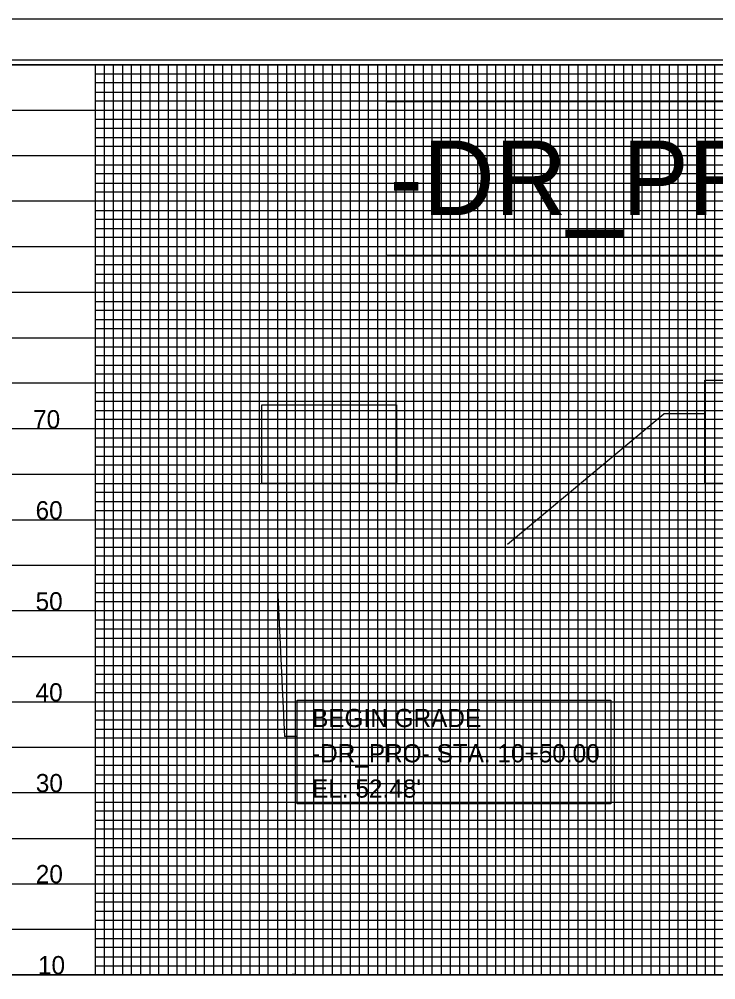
# Model space of a CAD drawing. Extents: x 1019474 to 1021158, y 503201 to 504732.
# Drawn here: x 1020350 to 1020732, y 503773 to 504301 of the extents above; entities that cross this region are included whole.
import ezdxf

# ---------------------------------------------------------------- set-up
doc = ezdxf.new("R2010")
doc.units = 0
for name, color, linetype in [('Exist Vertical Profile Vertical Axis Label', 7, 'Continuous'), ('Prop Grid Mask', 7, 'Continuous'), ('Prop Vertical Profile Grade Label', 7, 'Continuous'), ('Prop VPI Label', 7, 'Continuous'), ('Scratch_Level_0', 7, 'Continuous'), ('Sheet Cutting Line CELL', 7, 'Continuous'), ('Sheet Layout Profile Border Port 1', 7, 'Continuous'), ('Sheet Layout Profile Border Port 2', 7, 'Continuous'), ('Sheet Plot Border Inside CELL', 7, 'Continuous'), ('Sheet Plot Border Outside CELL', 7, 'Continuous'), ('Sheet Profile CELL', 7, 'Continuous'), ('Sheet Profile Grid Major CELL', 7, 'Continuous'), ('Sheet Profile Grid Middle CELL', 7, 'Continuous'), ('Sheet Profile Grid Minor CELL', 7, 'Continuous')]:
    doc.layers.add(name, color=color, linetype=linetype)

msp = doc.modelspace()

# ---------------------------------------------------------------- linework, layer by layer
at = {"layer": 'Prop Grid Mask'}
for points in [[(1020551.1, 504255.58), (1020851.32, 504255.58), (1020851.32, 504170.85), (1020551.1, 504170.85)], [(1020725.91, 504102.51), (1020898.5, 504102.51), (1020898.5, 504045.7), (1020725.91, 504045.7)], [(1020482.77, 504088.87), (1020556.58, 504088.87), (1020556.58, 504045.64), (1020482.77, 504045.64)], [(1020502.03, 503926.64), (1020674.35, 503926.64), (1020674.35, 503869.72), (1020502.03, 503869.72)]]:
    msp.add_lwpolyline(points, close=True, dxfattribs=at)
at = {"layer": 'Prop Vertical Profile Grade Label'}
for p, q in [((1020617.51, 504012.38), (1020703.32, 504083.87)), ((1020726.37, 504083.87), (1020703.32, 504083.87)), ((1020491.22, 503988.11), (1020495.21, 503906.65)), ((1020502.12, 503906.65), (1020495.21, 503906.65))]:
    msp.add_line(p, q, dxfattribs=at)
at = {"layer": 'Scratch_Level_0'}
msp.add_lwpolyline([(1019691.22, 503775.7), (1019691.22, 504275.7), (1020941.22, 504275.7), (1020941.17, 504114.65), (1021091.22, 504114.65), (1021091.22, 503775.7)], close=True, dxfattribs=at)
at = {"layer": 'Sheet Cutting Line CELL'}
msp.add_line((1021158.22, 504300.7), (1019474.22, 504300.7), dxfattribs=at)
at = {"layer": 'Sheet Layout Profile Border Port 1'}
msp.add_lwpolyline([(1019691.22, 504114.65), (1019691.22, 503775.7), (1021091.22, 503775.7), (1021091.22, 504114.65)], dxfattribs=at)
at = {"layer": 'Sheet Layout Profile Border Port 2'}
msp.add_lwpolyline([(1019691.22, 504275.7), (1020941.22, 504275.7), (1020941.17, 504114.65), (1021091.22, 504114.65), (1021091.22, 503775.7), (1019691.22, 503775.7)], close=True, dxfattribs=at)
at = {"layer": 'Sheet Plot Border Inside CELL'}
msp.add_lwpolyline([(1019487.22, 503223.15), (1021153.72, 503223.15), (1021153.72, 504278.25), (1019487.22, 504278.25)], close=True, dxfattribs=at)
at = {"layer": 'Sheet Plot Border Outside CELL'}
msp.add_lwpolyline([(1019474.22, 503200.7), (1021158.22, 503200.7), (1021158.22, 504300.7), (1019474.22, 504300.7)], close=True, dxfattribs=at)
at = {"layer": 'Sheet Profile CELL'}
msp.add_line((1019641.22, 503775.7), (1021141.22, 503775.7), dxfattribs=at)
msp.add_lwpolyline([(1021141.22, 504275.7), (1019641.22, 504275.7), (1019641.22, 503225.7), (1021141.22, 503225.7)], close=True, dxfattribs=at)
at = {"layer": 'Sheet Profile Grid Major CELL'}
for p, q in [((1020341.22, 504275.7), (1020391.22, 504275.7)), ((1020391.22, 504275.7), (1020391.22, 503775.7)), ((1020441.22, 503775.7), (1020441.22, 504275.7)), ((1020441.22, 504275.7), (1020491.22, 504275.7)), ((1020491.22, 504275.7), (1020491.22, 503775.7)), ((1020541.22, 503775.7), (1020541.22, 504275.7)), ((1020541.22, 504275.7), (1020591.22, 504275.7)), ((1020591.22, 504275.7), (1020591.22, 503775.7)), ((1020641.22, 503775.7), (1020641.22, 504275.7)), ((1020641.22, 504275.7), (1020691.22, 504275.7)), ((1020691.22, 504275.7), (1020691.22, 503775.7)), ((1020391.22, 503775.7), (1020441.22, 503775.7)), ((1020491.22, 503775.7), (1020541.22, 503775.7)), ((1020591.22, 503775.7), (1020641.22, 503775.7)), ((1020691.22, 503775.7), (1020741.22, 503775.7))]:
    msp.add_line(p, q, dxfattribs=at)
for points in [[(1020941.17, 504225.7), (1019641.22, 504225.7)], [(1020941.17, 504175.7), (1019641.22, 504175.7), (1019641.22, 504125.7), (1020941.17, 504125.7)], [(1021141.22, 504075.7), (1019641.22, 504075.7), (1019641.22, 504025.7), (1021141.22, 504025.7)], [(1021141.22, 503975.7), (1019641.22, 503975.7), (1019641.22, 503925.7), (1021141.22, 503925.7)], [(1021141.22, 503875.7), (1019641.22, 503875.7), (1019641.22, 503875.7), (1019641.22, 503825.7), (1021141.22, 503825.7)]]:
    msp.add_lwpolyline(points, dxfattribs=at)
at = {"layer": 'Sheet Profile Grid Middle CELL'}
for p, q in [((1020466.22, 503775.7), (1020466.22, 504275.7)), ((1020466.22, 504275.7), (1020516.22, 504275.7)), ((1020516.22, 504275.7), (1020516.22, 503775.7)), ((1020566.22, 503775.7), (1020566.22, 504275.7)), ((1020566.22, 504275.7), (1020616.22, 504275.7)), ((1020616.22, 504275.7), (1020616.22, 503775.7)), ((1020666.22, 503775.7), (1020666.22, 504275.7)), ((1020666.22, 504275.7), (1020716.22, 504275.7)), ((1020716.22, 504275.7), (1020716.22, 503775.7)), ((1020441.22, 503775.7), (1020466.22, 503775.7)), ((1020516.22, 503775.7), (1020566.22, 503775.7)), ((1020616.22, 503775.7), (1020666.22, 503775.7)), ((1020716.22, 503775.7), (1020766.22, 503775.7))]:
    msp.add_line(p, q, dxfattribs=at)
for points in [[(1020391.22, 503775.7), (1020416.22, 503775.7), (1020416.22, 504275.7), (1020441.22, 504275.7)], [(1019641.22, 504250.7), (1020941.22, 504250.7)], [(1020941.17, 504200.7), (1019641.22, 504200.7), (1019641.22, 504150.7), (1020941.17, 504150.7)], [(1021141.22, 504100.7), (1019641.22, 504100.7), (1019641.22, 504050.7), (1021141.22, 504050.7)], [(1021141.22, 504000.7), (1019641.22, 504000.7), (1019641.22, 503950.7), (1021141.22, 503950.7)], [(1021141.22, 503900.7), (1019641.22, 503900.7), (1019641.22, 503850.7), (1021141.22, 503850.7)], [(1021141.22, 503800.7), (1019641.22, 503800.7)]]:
    msp.add_lwpolyline(points, dxfattribs=at)
at = {"layer": 'Sheet Profile Grid Minor CELL'}
for p, q in [((1020391.22, 504270.7), (1020441.22, 504270.7)), ((1020441.22, 504270.7), (1020941.22, 504270.7)), ((1020441.22, 504265.7), (1020391.22, 504265.7)), ((1020941.22, 504265.7), (1020441.22, 504265.7)), ((1020391.22, 504260.7), (1020441.22, 504260.7)), ((1020441.22, 504260.7), (1020941.22, 504260.7)), ((1020441.22, 504255.7), (1020391.22, 504255.7)), ((1020941.22, 504255.7), (1020441.22, 504255.7)), ((1020391.22, 504245.7), (1020441.22, 504245.7)), ((1020441.22, 504245.7), (1020941.22, 504245.7)), ((1020441.22, 504240.7), (1020391.22, 504240.7)), ((1020941.22, 504240.7), (1020441.22, 504240.7)), ((1020391.22, 504235.7), (1020441.22, 504235.7)), ((1020441.22, 504235.7), (1020941.22, 504235.7)), ((1020441.22, 504230.7), (1020391.22, 504230.7)), ((1020941.22, 504230.7), (1020441.22, 504230.7)), ((1020391.22, 504220.7), (1020441.22, 504220.7)), ((1020441.22, 504220.7), (1020941.17, 504220.7)), ((1020441.22, 504215.7), (1020391.22, 504215.7)), ((1020941.17, 504215.7), (1020441.22, 504215.7)), ((1020391.22, 504210.7), (1020441.22, 504210.7)), ((1020441.22, 504210.7), (1020941.17, 504210.7)), ((1020441.22, 504205.7), (1020391.22, 504205.7)), ((1020941.17, 504205.7), (1020441.22, 504205.7)), ((1020391.22, 504195.7), (1020441.22, 504195.7)), ((1020441.22, 504195.7), (1020941.17, 504195.7)), ((1020441.22, 504190.7), (1020391.22, 504190.7)), ((1020941.17, 504190.7), (1020441.22, 504190.7)), ((1020391.22, 504185.7), (1020441.22, 504185.7)), ((1020441.22, 504185.7), (1020941.17, 504185.7)), ((1020441.22, 504180.7), (1020391.22, 504180.7)), ((1020941.17, 504180.7), (1020441.22, 504180.7)), ((1020391.22, 504170.7), (1020441.22, 504170.7)), ((1020441.22, 504170.7), (1020941.17, 504170.7)), ((1020441.22, 504165.7), (1020391.22, 504165.7)), ((1020941.17, 504165.7), (1020441.22, 504165.7)), ((1020391.22, 504160.7), (1020441.22, 504160.7)), ((1020441.22, 504160.7), (1020941.17, 504160.7)), ((1020441.22, 504155.7), (1020391.22, 504155.7)), ((1020941.17, 504155.7), (1020441.22, 504155.7)), ((1020391.22, 504145.7), (1020441.22, 504145.7)), ((1020441.22, 504145.7), (1020941.17, 504145.7)), ((1020441.22, 504140.7), (1020391.22, 504140.7)), ((1020941.17, 504140.7), (1020441.22, 504140.7)), ((1020391.22, 504135.7), (1020441.22, 504135.7)), ((1020441.22, 504130.7), (1020391.22, 504130.7)), ((1020441.22, 504135.7), (1020941.17, 504135.7)), ((1020941.17, 504130.7), (1020441.22, 504130.7)), ((1020391.22, 504120.7), (1020441.22, 504120.7)), ((1020441.22, 504120.7), (1020941.22, 504120.7)), ((1020441.22, 504115.7), (1020391.22, 504115.7)), ((1020941.22, 504115.7), (1020441.22, 504115.7)), ((1020391.22, 504110.7), (1020441.22, 504110.7)), ((1020441.22, 504110.7), (1021091.22, 504110.7)), ((1020441.22, 504105.7), (1020391.22, 504105.7)), ((1021091.22, 504105.7), (1020441.22, 504105.7)), ((1020391.22, 504095.7), (1020441.22, 504095.7)), ((1020441.22, 504095.7), (1021091.22, 504095.7)), ((1020441.22, 504090.7), (1020391.22, 504090.7)), ((1021091.22, 504090.7), (1020441.22, 504090.7)), ((1020391.22, 504085.7), (1020441.22, 504085.7)), ((1020441.22, 504085.7), (1021091.22, 504085.7)), ((1020441.22, 504080.76), (1020391.22, 504080.77)), ((1021091.22, 504080.7), (1020441.22, 504080.77)), ((1020391.22, 504070.7), (1020441.22, 504070.7)), ((1020441.22, 504070.7), (1021091.22, 504070.7)), ((1020441.22, 504065.7), (1020391.22, 504065.7)), ((1021091.22, 504065.7), (1020441.22, 504065.7)), ((1020391.22, 504060.7), (1020441.22, 504060.7)), ((1020441.22, 504060.7), (1021091.22, 504060.7)), ((1020441.22, 504055.7), (1020391.22, 504055.7)), ((1021091.22, 504055.7), (1020441.22, 504055.7)), ((1020391.22, 504045.7), (1020441.22, 504045.7)), ((1020441.22, 504045.7), (1021091.22, 504045.7)), ((1020441.22, 504040.7), (1020391.22, 504040.7)), ((1020391.22, 504035.7), (1020441.22, 504035.7)), ((1021091.22, 504040.7), (1020441.22, 504040.7)), ((1020441.22, 504035.7), (1021091.22, 504035.7)), ((1020441.22, 504030.7), (1020391.22, 504030.7)), ((1021091.22, 504030.7), (1020441.22, 504030.7)), ((1020391.22, 504020.7), (1020441.22, 504020.7)), ((1020441.22, 504020.7), (1021091.22, 504020.7)), ((1020441.22, 504015.7), (1020391.22, 504015.7)), ((1021091.22, 504015.7), (1020441.22, 504015.7)), ((1020391.22, 504010.7), (1020441.22, 504010.7)), ((1020441.22, 504010.7), (1021091.22, 504010.7)), ((1020441.22, 504005.7), (1020391.22, 504005.7)), ((1021091.22, 504005.7), (1020441.22, 504005.7)), ((1020391.22, 503995.7), (1020441.22, 503995.7)), ((1020441.22, 503995.7), (1021091.22, 503995.7)), ((1020441.22, 503990.7), (1020391.22, 503990.7)), ((1021091.22, 503990.7), (1020441.22, 503990.7)), ((1020391.22, 503985.7), (1020441.22, 503985.7)), ((1020441.22, 503985.7), (1021091.22, 503985.7)), ((1020441.22, 503980.7), (1020391.22, 503980.7)), ((1021091.22, 503980.7), (1020441.22, 503980.7)), ((1020391.22, 503970.7), (1020441.22, 503970.7)), ((1020441.22, 503970.7), (1021091.22, 503970.7)), ((1020441.22, 503965.7), (1020391.22, 503965.7)), ((1021091.22, 503965.7), (1020441.22, 503965.7)), ((1020391.22, 503960.7), (1020441.22, 503960.7)), ((1020441.22, 503960.7), (1021091.22, 503960.7)), ((1020441.22, 503955.7), (1020391.22, 503955.7)), ((1021091.22, 503955.7), (1020441.22, 503955.7)), ((1020391.22, 503945.7), (1020441.22, 503945.7)), ((1020441.22, 503940.7), (1020391.22, 503940.7)), ((1020441.22, 503945.7), (1021091.22, 503945.7)), ((1021091.22, 503940.7), (1020441.22, 503940.7)), ((1020391.22, 503935.7), (1020441.22, 503935.7)), ((1020441.22, 503935.7), (1021091.22, 503935.7)), ((1020441.22, 503930.7), (1020391.22, 503930.7)), ((1021091.22, 503930.7), (1020441.22, 503930.7)), ((1020391.22, 503920.7), (1020441.22, 503920.7)), ((1020441.22, 503920.7), (1021091.22, 503920.7)), ((1020441.22, 503915.7), (1020391.22, 503915.7)), ((1021091.22, 503915.7), (1020441.22, 503915.7)), ((1020391.22, 503910.7), (1020441.22, 503910.7)), ((1020441.22, 503910.7), (1021091.22, 503910.7)), ((1020441.22, 503905.7), (1020391.22, 503905.7)), ((1021091.22, 503905.7), (1020441.22, 503905.7)), ((1020391.22, 503895.7), (1020441.22, 503895.7)), ((1020441.22, 503895.7), (1021091.22, 503895.7)), ((1020441.22, 503890.7), (1020391.22, 503890.7)), ((1021091.22, 503890.7), (1020441.22, 503890.7)), ((1020391.22, 503885.7), (1020441.22, 503885.7)), ((1020441.22, 503885.7), (1021091.22, 503885.7)), ((1020441.22, 503880.7), (1020391.22, 503880.7)), ((1021091.22, 503880.7), (1020441.22, 503880.7)), ((1020391.22, 503870.7), (1020441.22, 503870.7)), ((1020441.22, 503870.7), (1021091.22, 503870.7)), ((1020441.22, 503865.7), (1020391.22, 503865.7)), ((1021091.22, 503865.7), (1020441.22, 503865.7)), ((1020391.22, 503860.7), (1020441.22, 503860.7)), ((1020441.22, 503860.7), (1021091.22, 503860.7)), ((1020441.22, 503855.7), (1020391.22, 503855.7)), ((1021091.22, 503855.7), (1020441.22, 503855.7)), ((1020391.22, 503845.7), (1020441.22, 503845.7)), ((1020441.22, 503845.7), (1021091.22, 503845.7)), ((1020441.22, 503840.7), (1020391.22, 503840.7)), ((1021091.22, 503840.7), (1020441.22, 503840.7)), ((1020391.22, 503835.7), (1020441.22, 503835.7)), ((1020441.22, 503835.7), (1021091.22, 503835.7)), ((1020441.22, 503830.7), (1020391.22, 503830.7)), ((1021091.22, 503830.7), (1020441.22, 503830.7)), ((1020391.22, 503820.7), (1020441.22, 503820.7)), ((1020441.22, 503820.7), (1021091.22, 503820.7)), ((1020441.22, 503815.7), (1020391.22, 503815.7)), ((1021091.22, 503815.7), (1020441.22, 503815.7)), ((1020391.22, 503810.7), (1020441.22, 503810.7)), ((1020441.22, 503810.7), (1021091.22, 503810.7)), ((1020441.22, 503805.7), (1020391.22, 503805.7)), ((1021091.22, 503805.7), (1020441.22, 503805.7)), ((1020391.22, 503795.7), (1020441.22, 503795.7)), ((1020441.22, 503795.7), (1021091.22, 503795.7)), ((1020441.22, 503790.7), (1020391.22, 503790.7)), ((1021091.22, 503790.7), (1020441.22, 503790.7)), ((1020391.22, 503785.7), (1020441.22, 503785.7)), ((1020441.22, 503785.7), (1021091.22, 503785.7)), ((1020391.22, 503780.7), (1020441.22, 503780.7)), ((1020441.22, 503780.7), (1021091.22, 503780.7))]:
    msp.add_line(p, q, dxfattribs=at)
for points in [[(1020391.22, 504275.7), (1020396.22, 504275.7), (1020396.22, 503775.7), (1020401.22, 503775.7), (1020401.22, 504275.7), (1020406.22, 504275.7), (1020406.22, 503775.7), (1020411.22, 503775.7), (1020411.22, 504275.7), (1020421.22, 504275.7), (1020421.22, 503775.7), (1020426.22, 503775.7), (1020426.22, 504275.7), (1020431.22, 504275.7), (1020431.22, 503775.7), (1020436.22, 503775.7), (1020436.22, 504275.7), (1020441.22, 504275.7)], [(1020441.22, 504275.7), (1020446.22, 504275.7), (1020446.22, 503775.7), (1020451.22, 503775.7), (1020451.22, 504275.7), (1020456.22, 504275.7), (1020456.22, 503775.7), (1020461.22, 503775.7), (1020461.22, 504275.7), (1020471.22, 504275.7), (1020471.22, 503775.7), (1020476.22, 503775.7), (1020476.22, 504275.7), (1020481.22, 504275.7), (1020481.22, 503775.7), (1020486.22, 503775.7), (1020486.22, 504275.7), (1020496.22, 504275.7), (1020496.22, 503775.7), (1020500.92, 503776.25), (1020501.22, 503775.7), (1020501.22, 504275.7), (1020506.22, 504275.7), (1020506.22, 503775.7), (1020511.22, 503775.7), (1020511.22, 504275.7), (1020521.22, 504275.7), (1020521.22, 503775.7), (1020526.22, 503775.7)], [(1020526.22, 503775.7), (1020526.22, 504275.7), (1020531.22, 504275.7), (1020531.22, 503775.7), (1020536.22, 503775.7), (1020536.22, 504275.7), (1020546.22, 504275.7), (1020546.22, 503775.7), (1020551.22, 503775.7), (1020551.22, 504275.7), (1020556.22, 504275.7), (1020556.22, 503775.7), (1020561.22, 503775.7), (1020561.22, 504275.7), (1020571.22, 504275.7), (1020571.22, 503775.7), (1020576.22, 503775.7), (1020576.22, 504275.7), (1020581.22, 504275.7), (1020581.22, 503775.7), (1020586.22, 503775.7), (1020586.22, 504275.7), (1020596.22, 504275.7), (1020596.22, 503775.7), (1020601.22, 503775.7), (1020601.22, 504275.7), (1020606.22, 504275.7), (1020606.22, 503775.7), (1020611.22, 503775.7), (1020611.22, 504275.7), (1020621.22, 504275.7), (1020621.22, 503775.7), (1020626.22, 503775.7), (1020626.22, 504275.7), (1020631.22, 504275.7), (1020631.22, 503775.7), (1020636.22, 503775.7), (1020636.22, 504275.7), (1020646.22, 504275.7), (1020646.22, 503775.7), (1020651.22, 503775.7), (1020651.22, 504275.7), (1020656.22, 504275.7), (1020656.22, 503775.7), (1020661.22, 503775.7), (1020661.22, 504275.7), (1020671.22, 504275.7), (1020671.22, 503775.7), (1020676.22, 503775.7), (1020676.22, 504275.7), (1020681.22, 504275.7), (1020681.22, 503775.7), (1020686.22, 503775.7), (1020686.22, 504275.7), (1020696.22, 504275.7), (1020696.22, 503775.7), (1020701.22, 503775.7), (1020701.22, 504275.7), (1020706.22, 504275.7), (1020706.22, 503775.7), (1020711.22, 503775.7), (1020711.22, 504275.7), (1020721.22, 504275.7), (1020721.22, 503775.7), (1020726.22, 503775.7), (1020726.22, 504275.7), (1020731.22, 504275.7), (1020731.22, 503775.7), (1020736.22, 503775.7)]]:
    msp.add_lwpolyline(points, dxfattribs=at)

# ---------------------------------------------------------------- texts
at = {"layer": 'Exist Vertical Profile Vertical Axis Label'}
for s, p in [('70', (1020357.11, 504075.95)), ('60', (1020358.49, 504025.95)), ('50', (1020358.49, 503975.95)), ('40', (1020358.49, 503925.95)), ('30', (1020358.61, 503876.1)), ('20', (1020358.61, 503826.1)), ('10', (1020359.8, 503776.1))]:
    msp.add_text(s, height=10, dxfattribs=at).set_placement(p)
at = {"layer": 'Prop Vertical Profile Grade Label'}
for s, p in [('BEGIN GRADE', (1020510.25, 503911.86)), ('-DR_PRO- STA. 10+50.00', (1020510.25, 503892.49)), ("EL. 52.48'", (1020510.25, 503873.11))]:
    msp.add_text(s, height=10, rotation=360, dxfattribs=at).set_placement(p)
at = {"layer": 'Prop VPI Label'}
msp.add_text('-DR_PRO-', height=40.95, dxfattribs=at).set_placement((1020552.76, 504193.09))

doc.saveas('drawing.dxf')
